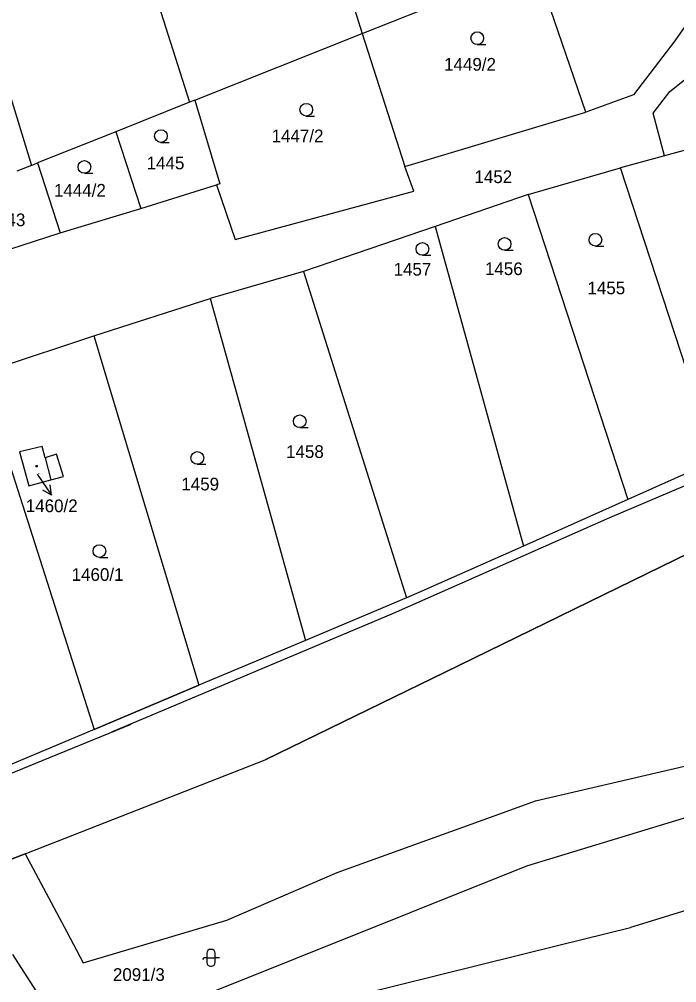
# Model space of a CAD drawing. Extents: x -805730 to -804640, y -1150889 to -1150366.
# Drawn here: x -805002.2 to -804924.5, y -1150618.3 to -1150504.4 of the extents above; entities that cross this region are included whole.
import ezdxf

# ---------------------------------------------------------------- set-up
doc = ezdxf.new("R2010")
doc.units = 0
for name, color, linetype in [('Default', 7, 'Continuous'), ('kn_celek - Cisla parcel pomocna', 7, 'Continuous'), ('kn_celek - Cisla pozemkovych parcel', 7, 'Continuous'), ('kn_celek - Cisla stavebnich parcel', 7, 'Continuous'), ('kn_celek - Hranice parcel', 7, 'Continuous'), ('kn_celek - Vnitrni kresby', 7, 'Continuous'), ('kn_celek - Znacky budov', 7, 'Continuous'), ('kn_celek - Znacky kultur', 7, 'Continuous'), ('plochy - SZDC', 7, 'Continuous'), ('PSR_C2_2_trasa_Vimperk - Kabelová trasa', 7, 'Continuous')]:
    doc.layers.add(name, color=color, linetype=linetype)

# ---------------------------------------------------------------- blocks, each defined once
blk = doc.blocks.new('304')
at = {"layer": 'Default'}
blk.add_line((-0.1, 0), (9.9, 0), dxfattribs=at)
blk.add_circle((-0.1, 7.5), 7.5, dxfattribs=at)
blk = doc.blocks.new('316')
at = {"layer": 'Default'}
for p, q in [((-5, 15.5), (-5, 4.5)), ((0.5, 20), (-0.5, 20)), ((5, 4.5), (5, 15.5)), ((-8.3, 10), (-10, 8.1)), ((-5, 10), (-8.3, 10)), ((-5, 10), (5, 10)), ((-0.5, 0), (0.5, 0)), ((10, 10), (5, 10))]:
    blk.add_line(p, q, dxfattribs=at)
for centre, start, end in [((-0.5, 15.5), 90, 180), ((0.5, 15.5), 0, 90), ((-0.5, 4.5), 180, 270), ((0.5, 4.5), 270, 0)]:
    blk.add_arc(centre, 4.5, start, end, dxfattribs=at)
blk = doc.blocks.new('402')
at = {"layer": 'Default'}
for p, q in [((-0.8, 0.8), (0.7, 0.8)), ((-0.8, 0.8), (-0.8, -0.7)), ((0.7, 0.8), (0.7, -0.7)), ((0.7, -0.7), (-0.8, -0.7))]:
    blk.add_line(p, q, dxfattribs=at)
blk = doc.blocks.new('Z61')
at = {"layer": 'Default'}
for p, q in [((0, 0), (30, 0)), ((30, 0), (19.2, 5.3)), ((30, 0), (19.2, -5.3))]:
    blk.add_line(p, q, dxfattribs=at)

msp = doc.modelspace()

# ---------------------------------------------------------------- linework, layer by layer
at = {"layer": 'kn_celek - Hranice parcel'}
for p, q in [((-804971.65, -1150474.85), (-804961.69, -1150506.13)), ((-804992.2, -1150482.63), (-804982.1, -1150514.26)), ((-804961.69, -1150506.13), (-804941.26, -1150497.99)), ((-804935.25, -1150515.44), (-804941.26, -1150497.99)), ((-805006.12, -1150504.36), (-805000.8, -1150521.71)), ((-804923.01, -1150504.53), (-804924.76, -1150507)), ((-804981.49, -1150514.02), (-804961.69, -1150506.13)), ((-804961.69, -1150506.13), (-804956.66, -1150521.83)), ((-804924.76, -1150507), (-804929.64, -1150513.37)), ((-804925.34, -1150512.97), (-804922.03, -1150510.36)), ((-804929.64, -1150513.37), (-804935.25, -1150515.44)), ((-804927.29, -1150515.56), (-804925.34, -1150512.97)), ((-804982.1, -1150514.26), (-804990.82, -1150517.74)), ((-804981.49, -1150514.02), (-804982.1, -1150514.26)), ((-804981.49, -1150514.02), (-804978.53, -1150523.9)), ((-804956.66, -1150521.83), (-804935.25, -1150515.44)), ((-804925.98, -1150520.59), (-804927.29, -1150515.56)), ((-804990.82, -1150517.74), (-805000.1, -1150521.43)), ((-804990.82, -1150517.74), (-804987.87, -1150526.81)), ((-804920.55, -1150519.13), (-804925.98, -1150520.59)), ((-805000.8, -1150521.71), (-805000.1, -1150521.43)), ((-805000.1, -1150521.43), (-804997.39, -1150529.68)), ((-804925.98, -1150520.59), (-804931.17, -1150521.99)), ((-805000.8, -1150521.71), (-805002.53, -1150522.4)), ((-804955.59, -1150524.76), (-804956.66, -1150521.83)), ((-804942.09, -1150525.15), (-804931.17, -1150521.99)), ((-804919.88, -1150556.55), (-804931.17, -1150521.99)), ((-804978.53, -1150523.9), (-804978.94, -1150524.03)), ((-804987.87, -1150526.81), (-804978.94, -1150524.03)), ((-804978.94, -1150524.03), (-804976.73, -1150530.46)), ((-804976.73, -1150530.46), (-804955.59, -1150524.76)), ((-804942.09, -1150525.15), (-804953.07, -1150528.93)), ((-804942.09, -1150525.15), (-804930.31, -1150561.21)), ((-804997.39, -1150529.68), (-804987.87, -1150526.81)), ((-804953.07, -1150528.93), (-804968.63, -1150534.27)), ((-804953.07, -1150528.93), (-804942.65, -1150566.71)), ((-805006.9, -1150532.75), (-804997.39, -1150529.68)), ((-804968.63, -1150534.27), (-804979.68, -1150537.43)), ((-804968.63, -1150534.27), (-804956.48, -1150572.84)), ((-804993.42, -1150541.84), (-804979.68, -1150537.43)), ((-804979.68, -1150537.43), (-804968.41, -1150577.86)), ((-805006.87, -1150546.34), (-804993.42, -1150541.84)), ((-804993.42, -1150541.84), (-804981, -1150583.16)), ((-805006.87, -1150546.34), (-804993.4, -1150588.37)), ((-804999.53, -1150554.92), (-805002.21, -1150555.58)), ((-805002.21, -1150555.58), (-805001.12, -1150559.6)), ((-804999.18, -1150556.26), (-804999.53, -1150554.92)), ((-804997.82, -1150555.84), (-804999.18, -1150556.26)), ((-804997.03, -1150558.5), (-804997.82, -1150555.84)), ((-804919.88, -1150556.55), (-804930.31, -1150561.21)), ((-805001.12, -1150559.6), (-804998.49, -1150558.89)), ((-804998.49, -1150558.89), (-804997.03, -1150558.5)), ((-804930.31, -1150561.21), (-804942.65, -1150566.71)), ((-804942.65, -1150566.71), (-804954.99, -1150572.21)), ((-804923.02, -1150567.51), (-804951.89, -1150581.61)), ((-804956.48, -1150572.84), (-804968.41, -1150577.86)), ((-804954.99, -1150572.21), (-804956.48, -1150572.84)), ((-804968.41, -1150577.86), (-804981, -1150583.16)), ((-804951.89, -1150581.61), (-804973.16, -1150591.99)), ((-804993.4, -1150588.37), (-804981, -1150583.16)), ((-804942.25, -1150604.51), (-804885.76, -1150587.34)), ((-804993.4, -1150588.37), (-805005.74, -1150593.57)), ((-804941.23, -1150596.81), (-804915.29, -1150590.76)), ((-805001.53, -1150603.08), (-804973.16, -1150591.99)), ((-804945.01, -1150598.18), (-804941.23, -1150596.81)), ((-804964.64, -1150605.3), (-804945.01, -1150598.18)), ((-805001.53, -1150603.08), (-805004.51, -1150604.24)), ((-805001.53, -1150603.08), (-804996.63, -1150612.29)), ((-804986.38, -1150622.16), (-804942.25, -1150604.51)), ((-804977.72, -1150610.93), (-804964.64, -1150605.3)), ((-804907.43, -1150604.85), (-804929.98, -1150611.77)), ((-804994.68, -1150615.96), (-804977.72, -1150610.93)), ((-804996.63, -1150612.29), (-804994.68, -1150615.96)), ((-804938.45, -1150613.86), (-804929.98, -1150611.77)), ((-804973.51, -1150622.54), (-804938.45, -1150613.86)), ((-805003.05, -1150614.96), (-804998.33, -1150622.28))]:
    msp.add_line(p, q, dxfattribs=at)
at = {"layer": 'kn_celek - Vnitrni kresby'}
msp.add_line((-804999.18, -1150556.26), (-804998.49, -1150558.89), dxfattribs=at)
at = {"layer": 'plochy - SZDC'}
for p, q in [((-804919.88, -1150556.55), (-804930.31, -1150561.21)), ((-804930.31, -1150561.21), (-804942.65, -1150566.71)), ((-804942.65, -1150566.71), (-804954.99, -1150572.21)), ((-804951.89, -1150581.61), (-804923.02, -1150567.51)), ((-804956.48, -1150572.84), (-804968.41, -1150577.86)), ((-804954.99, -1150572.21), (-804956.48, -1150572.84)), ((-804968.41, -1150577.86), (-804981, -1150583.16)), ((-804973.16, -1150591.99), (-804951.89, -1150581.61)), ((-804981, -1150583.16), (-804993.4, -1150588.37)), ((-804993.4, -1150588.37), (-805005.74, -1150593.57)), ((-805001.53, -1150603.08), (-804973.16, -1150591.99)), ((-805004.51, -1150604.24), (-805001.53, -1150603.08))]:
    msp.add_line(p, q, dxfattribs=at)
at = {"layer": 'PSR_C2_2_trasa_Vimperk - Kabelová trasa'}
for points in [[(-804861.61, -1150536.05), (-804874.49, -1150540.07), (-804895.8, -1150547.79), (-804932.46, -1150563.38), (-804958.05, -1150574.66), (-804991.35, -1150588.71)], [(-805122.45, -1150641.59), (-805112.53, -1150638.37), (-805102.25, -1150634.46), (-805084.03, -1150627.11), (-805075.4, -1150623.5), (-805060.17, -1150617.08), (-805047.9, -1150611.92), (-805039.79, -1150608.5), (-804989.01, -1150587.76)]]:
    msp.add_lwpolyline(points, dxfattribs=at)

# ---------------------------------------------------------------- block references
at = {"layer": 'kn_celek - Cisla parcel pomocna', "xscale": 0.10000000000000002, "yscale": 0.1, "rotation": -55.00791000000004}
msp.add_blockref('Z61', (-805000.14, -1150558.22), dxfattribs=at)
at = {"layer": 'kn_celek - Znacky budov', "xscale": 0.1, "yscale": 0.10000000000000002}
msp.add_blockref('402', (-805000.19, -1150557.26), dxfattribs=at)
at = {"layer": 'kn_celek - Znacky kultur', "xscale": 0.1, "yscale": 0.10000000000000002}
for name, p in [('304', (-804948.09, -1150507.43)), ('304', (-804968.31, -1150515.89)), ('304', (-804985.49, -1150519)), ('304', (-804994.53, -1150522.64)), ('304', (-804944.86, -1150531.74)), ('304', (-804934.12, -1150531.26)), ('304', (-804954.57, -1150532.34)), ('304', (-804969.08, -1150552.7)), ('304', (-804981.18, -1150557.04)), ('304', (-804992.76, -1150568.05)), ('316', (-804979.58, -1150616.37))]:
    msp.add_blockref(name, p, dxfattribs=at)

# ---------------------------------------------------------------- texts
at = {"layer": 'kn_celek - Cisla parcel pomocna'}
msp.add_text('1460/2', height=1.5, dxfattribs=at).set_placement((-805001.47, -1150562.7))
at = {"layer": 'kn_celek - Cisla pozemkovych parcel'}
for s, p in [('1449/2', (-804952.02, -1150510.52)), ('1447/2', (-804972.41, -1150518.98)), ('1445', (-804987.18, -1150522.18)), ('1452', (-804948.43, -1150523.81)), ('1444/2', (-804998.14, -1150525.41)), ('1443', (-805005.98, -1150528.9)), ('1457', (-804957.99, -1150534.74)), ('1456', (-804947.19, -1150534.68)), ('1455', (-804935.07, -1150536.95)), ('1458', (-804970.7, -1150556.29)), ('1459', (-804983.08, -1150560.13)), ('1460/1', (-804996.05, -1150570.82)), ('2091/3', (-804991.17, -1150618.1))]:
    msp.add_text(s, height=1.5, dxfattribs=at).set_placement(p)
at = {"layer": 'kn_celek - Cisla stavebnich parcel'}
msp.add_text('1460/2', height=0.1, dxfattribs=at).set_placement((-805000.14, -1150558.19))

doc.saveas('drawing.dxf')
